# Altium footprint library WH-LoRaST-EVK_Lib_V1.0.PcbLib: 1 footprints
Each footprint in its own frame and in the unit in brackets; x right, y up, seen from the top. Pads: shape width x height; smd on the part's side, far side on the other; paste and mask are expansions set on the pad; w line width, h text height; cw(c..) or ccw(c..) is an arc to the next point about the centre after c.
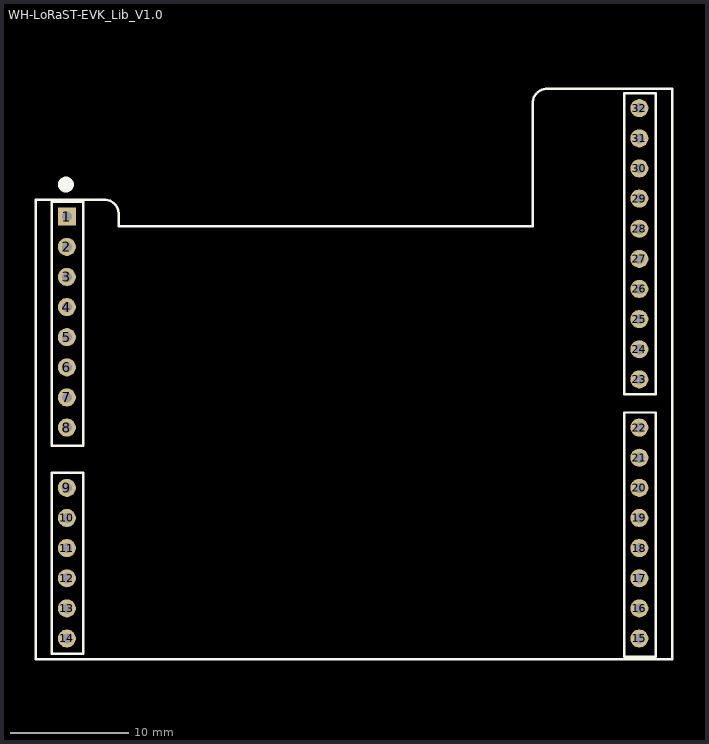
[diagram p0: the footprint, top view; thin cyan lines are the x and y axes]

## WH-LoRaST-EVK_Lib_V1.0 [mil]
pads (32):
  rect 60x60 hole 33.47: 1(-13797,-26381.57)
  round 60 hole 33.47: 2(-13797,-26481.57) 3(-13797,-26581.57) 4(-13797,-26681.57) 5(-13797,-26781.57) 6(-13797,-26881.57) 7(-13797,-26981.57) 8(-13797,-27081.57) 9(-13797,-27281.57) 10(-13797,-27381.57) 11(-13797,-27481.57) 12(-13797,-27581.57) 13(-13797,-27681.57) 14(-13797,-27781.57) 15(-11897,-27781.57) 16(-11897,-27681.57) 17(-11897,-27581.57) 18(-11897,-27481.57) 19(-11897,-27381.57) 20(-11897,-27281.57) 21(-11897,-27181.57) 22(-11897,-27081.57) 23(-11897,-26921.57) 24(-11897,-26821.57) 25(-11897,-26721.57) 26(-11897,-26621.57) 27(-11897,-26521.57) 28(-11897,-26421.57) 29(-11897,-26321.57) 30(-11897,-26221.57) 31(-11897,-26121.57) 32(-11897,-26021.57)
Top Overlay:
  circle w30: c-13800,-26275 r11.18
  lines w8: -13675,-26325.57 cw(c-13672,-26372.57) -13625,-26369.57 ; -13667,-26325.57 -13900,-26325.57 -13900,-27850 -11788,-27850 -11788,-26325.57 -11788,-25957.57 -12207,-25957.57 ccw(c-12204,-26004.57) -12251,-26007.57 -12251,-26413.57 -13625,-26413.57 -13625,-26369.58 ; -13847,-27831.57 -13742,-27831.57 -13742,-27231.57 -13847,-27231.57 -13847,-27831.57 ; -13847,-27141.57 -13847,-26331.57 -13742,-26331.57 -13742,-27141.57 -13847,-27141.57 ; -11947,-27841.57 -11947,-27031.57 -11842,-27031.57 -11842,-27841.57 -11947,-27841.57 ; -11947,-26971.57 -11947,-25971.57 -11842,-25971.57 -11842,-26971.57 -11947,-26971.57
